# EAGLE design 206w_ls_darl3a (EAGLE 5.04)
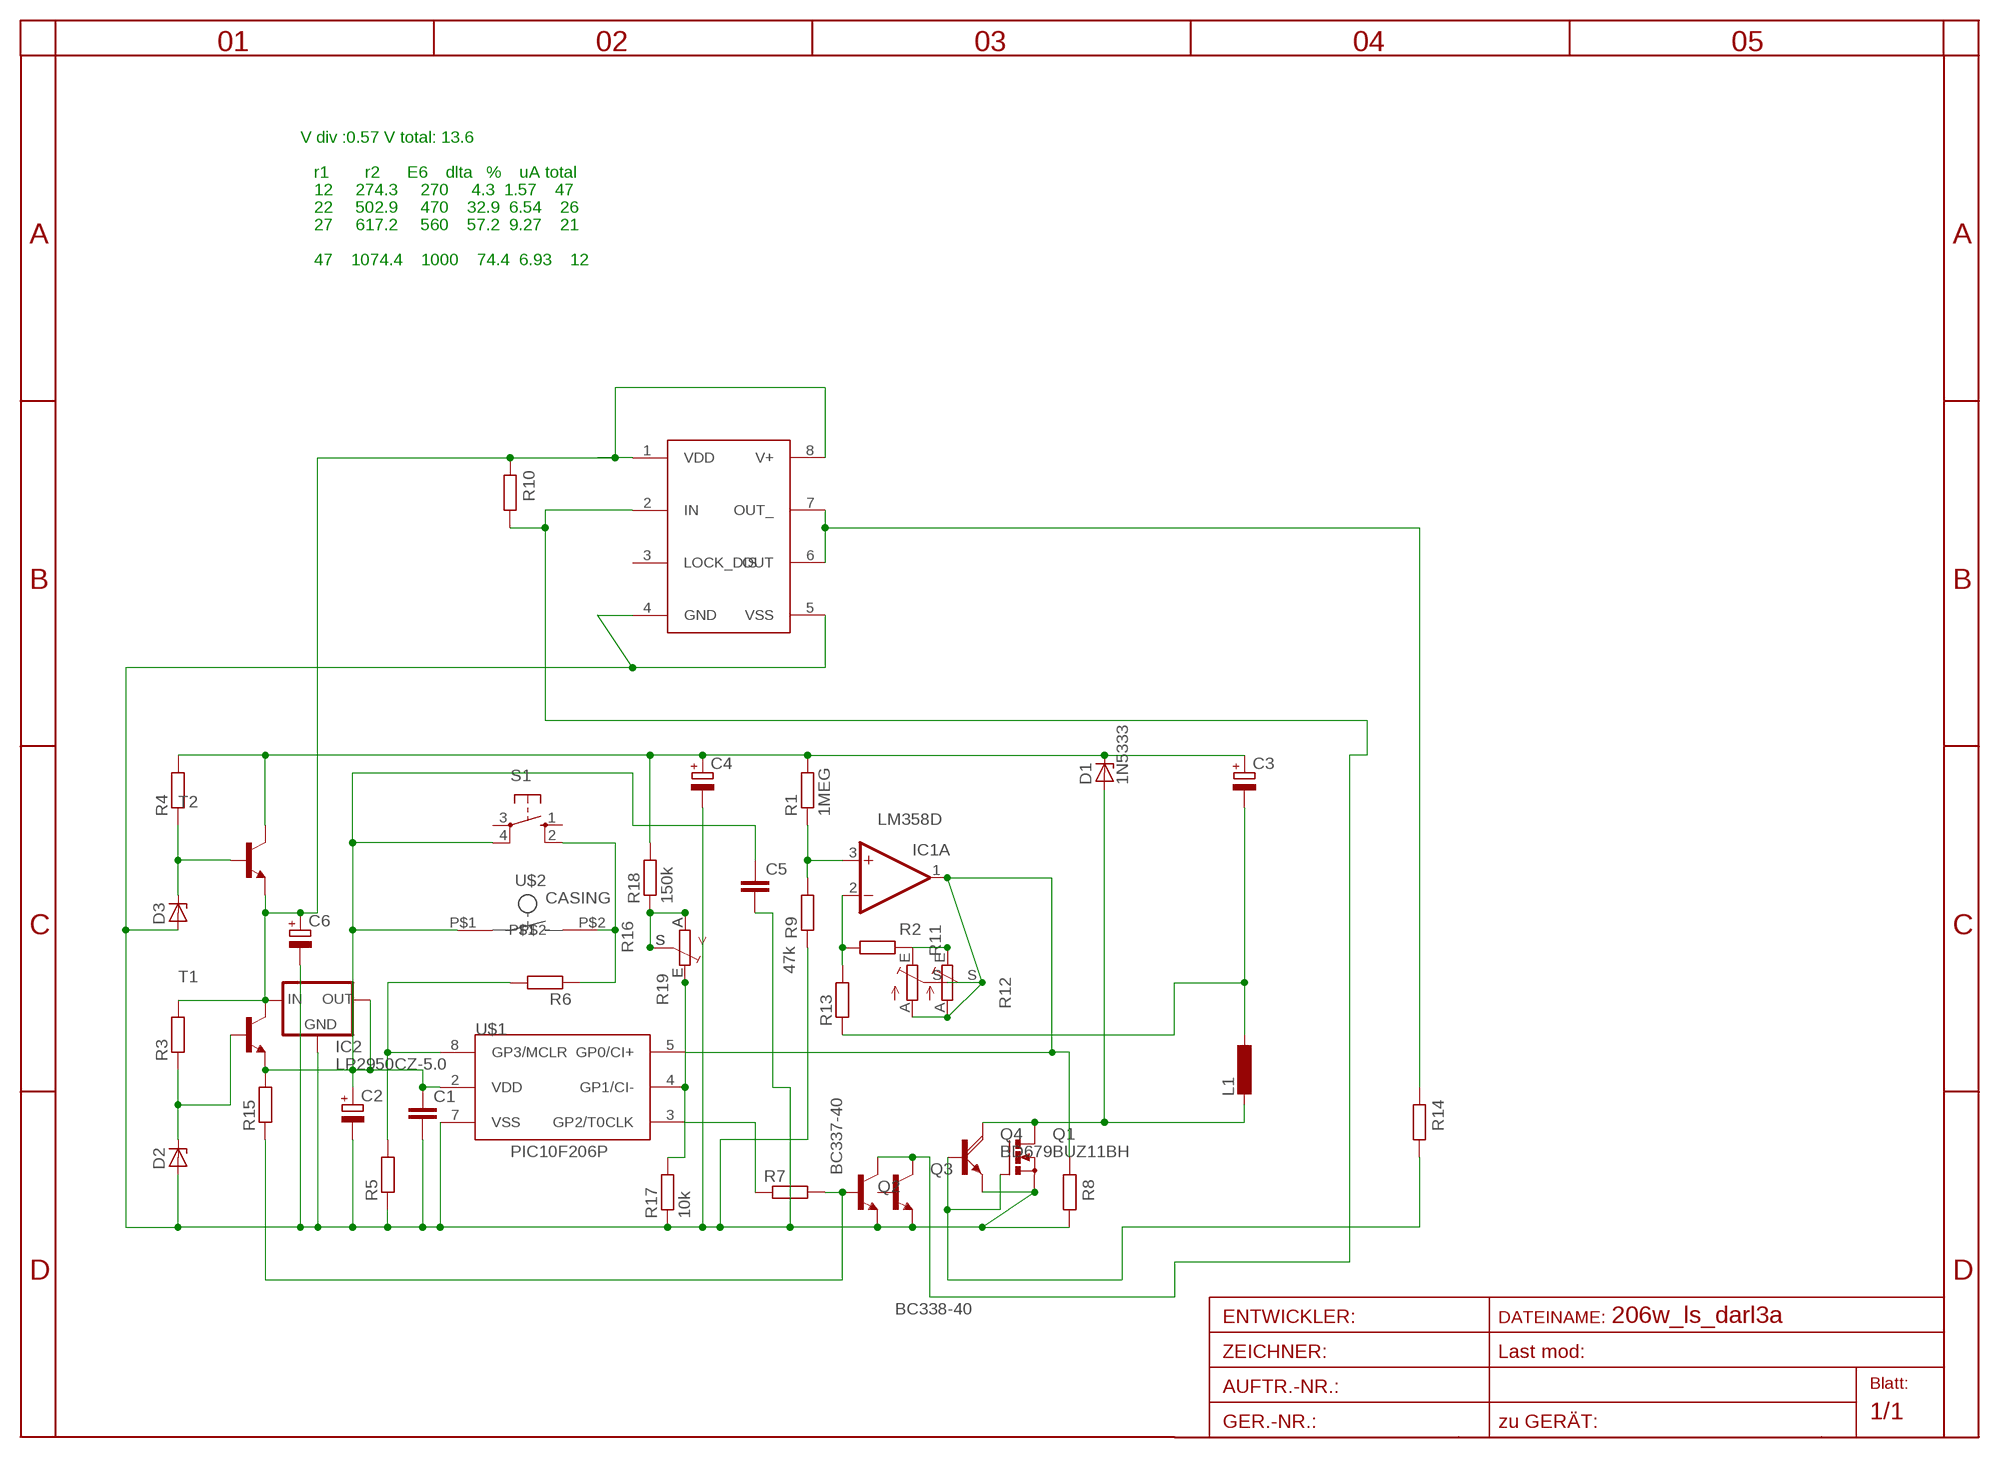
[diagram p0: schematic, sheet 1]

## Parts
C1  C-EU025-025X050  [C025-025X050]
C2  CPOL-EUE3.5-8  [E3,5-8]
C3  CPOL-EUE5-8.5  [E5-8,5]
C4  CPOL-EUE5-8.5  [E5-8,5]
C5  C-EU050-024X044  [C050-024X044]
C6  CPOL-EUE3.5-8  [E3,5-8]
D1  1N5333  [C1702-15]
D2  ZENER-DIODEZD-7.5  [ZDIO-7.5]
D3  ZENER-DIODEZD-7.5  [ZDIO-7.5]
IC1  LM358D  [SO08]
IC2  LP2950CZ-5.0  [TO92]
IC3  TC4432X  [SO-08]
L1  L-EU0207/10  [0207/10]
Q1  BUZ11BH  [TO220BH]
Q2  BC337-40  [TO92]
Q3  BC338-40  [TO92-EBC]
Q4  BD679  [TO126AV]
R1  1MEG  R-EU_0207/12  [0207/12]
R2  R-EU_0204/7  [0204/7]
R3  R-EU_0204/7  [0204/7]
R4  R-EU_0207/10  [0207/10]
R5  R-EU_0204/7  [0204/7]
R6  R-EU_0204/7  [0204/7]
R7  R-EU_0207/15  [0207/15]
R8  R-EU_0204/7  [0204/7]
R9  47k  R-EU_0204/7  [0204/7]
R10  R-EU_0204/7  [0204/7]
R11  TRIM_EU-CA6V  [CA6V]
R12  TRIM_EU-LI15  [LI15]
R13  R-EU_0207/40  [0207/40]
R14  R-EU_0204/2V  [0204V]
R15  R-EU_0204/5  [0204/5]
R16  TRIM_EU-LI15  [LI15]
R17  10k  R-EU_0204/7  [0204/7]
R18  150k  R-EU_0207/40  [0207/40]
R19  TRIM_EU-CA6V  [CA6V]
S1  10-XX  [B3F-10XX]
T1  -NPN-TO92-BCE  [TO92-BCE]
T2  -NPN-TO92-BCE  [TO92-BCE]
U$1  PIC10F206P  [DIL8]
U$2  CASING  [CASING]

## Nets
BB: IC3.2(IN) Q2.3(C) Q3.C R10.1
HOTSPOT: D1.A L1.2 Q1.D Q4.C
N$1: IC1.1(A:OUT) R8.2 R11.A R11.S R12.A R12.S U$1.5(GP0/CI+)
N$2: R2.1 R11.E R12.E
N$3: Q1.G Q4.B R14.1
N$5: R5.2 R6.2 U$1.8(GP3/MCLR)
N$6: D2.C R3.1 T1.B
N$7: R6.1 S1.2(S1) U$2.P$2
N$8: IC1.3(A:+IN) R1.1 R9.2
N$9: R7.1 U$1.3(GP2/T0CLK)
N$11: IC3.6(OUT) IC3.7(OUT_) R14.2
N$12: D3.C R4.1 T2.B
N$13: R16.A R16.S R18.1 R19.A R19.S
N$14: R16.E R17.2 R19.E U$1.4(GP1/CI-)
N$15: IC1.2(A:-IN) R2.2 R13.2
N$17: Q2.2(B) R7.2 R15.1
V60: C3.+ C4.+ D1.C R1.2 R4.2 R18.2 T2.C
V+: C1.1 C2.+ C5.1 IC2.1(OUT) R15.2 S1.4(P1) T1.E U$1.2(VDD) U$2.P$1
V-: C1.2 C2.- C4.- C5.2 C6.- D2.A D3.A IC2.2(GND) IC3.4(GND) IC3.5(VSS) Q1.S Q2.1(E) Q3.E Q4.E R5.1 R8.1 R9.1 R17.1 U$1.7(VSS)
VCC: C6.+ IC2.3(IN) IC3.1(VDD) IC3.8(V+) R3.2 R10.2 T1.C T2.E
VOUT: C3.- L1.1 R13.1
Unconnected: IC1.5(B:+IN) IC1.6(B:-IN) IC1.7(B:OUT) IC3.3(LOCK_DIS) Q3.B S1.1(S) S1.3(P)

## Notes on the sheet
- V div :0.57 V total: 13.6
- r1        r2      E6    dlta   %    uA total
- 12     274.3     270     4.3  1.57    47
- 22     502.9     470    32.9  6.54    26
- 27     617.2     560    57.2  9.27    21
- 47    1074.4    1000    74.4  6.93    12

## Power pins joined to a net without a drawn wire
V+: IC1.8(P:V+)
V-: IC1.4(P:V-)

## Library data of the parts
C1 C5 = rcl:C-EU: CAPACITOR, European symbol
C2-C4 C6 = rcl:CPOL-EU: POLARIZED CAPACITOR, European symbol
D1 = diode-1:1N5333: Z DIODE
D2 D3 = diode-1:ZENER-DIODE: Z-Diode
IC1 = linear4:LM358: OP AMP
IC2 = v-reg:LP2950?*: Source: http://cache.national.com/ds/LP/LP2950.pdf
IC3 = microchip:TC4432
L1 = rcl:L-EU: INDUCTOR, European symbol
Q1 = transistor-power:BUZ11: N-CHANNEL MOS FET
Q2 = transistor-npn:BC337*: NPN Transistor
Q3 = transistor-npn:BC338*: NPN Transistor
Q4 = transistor-power:BD679: NPN DARLINGTON TRANSISTOR
R1-R6 R8-R10 R14 R15 = rcl:R-EU_: RESISTOR, European symbol
R7 R13 R17 R18 = rcl-2:R-EU_: RESISTOR, European symbol
R11 R12 R16 R19 = pot:TRIM_EU-: POTENTIOMETER
S1 = switch-omron:10-XX: OMRON SWITCH
T1 T2 = transistor-neu-to92:*-NPN-: NPN Transistror
U$1 = microchip-5:PIC10F2*: uPC nW 0,25/0,5k Program Flash memory Comparator
U$2 = button:CASING

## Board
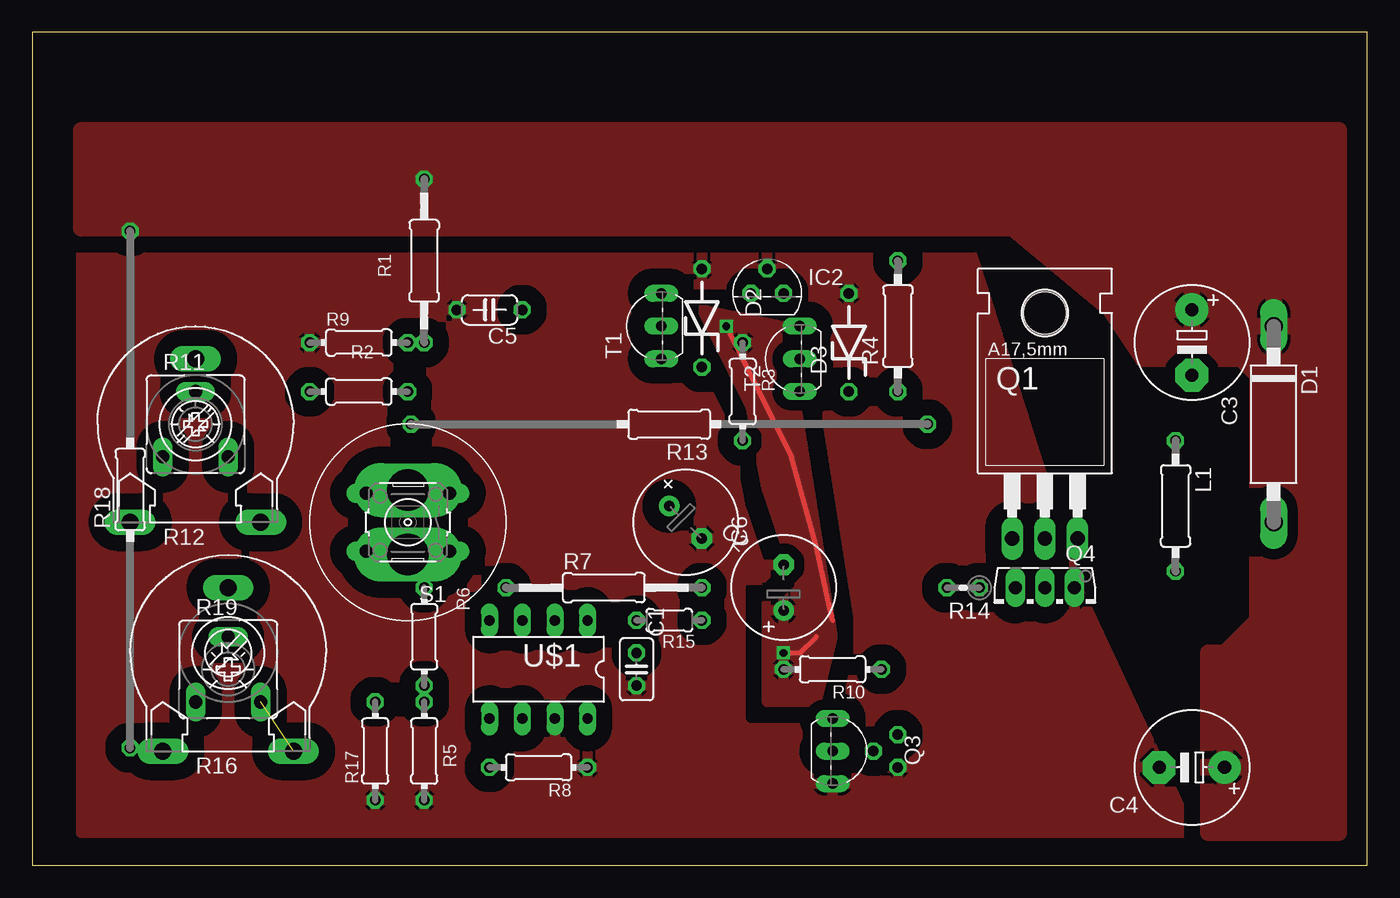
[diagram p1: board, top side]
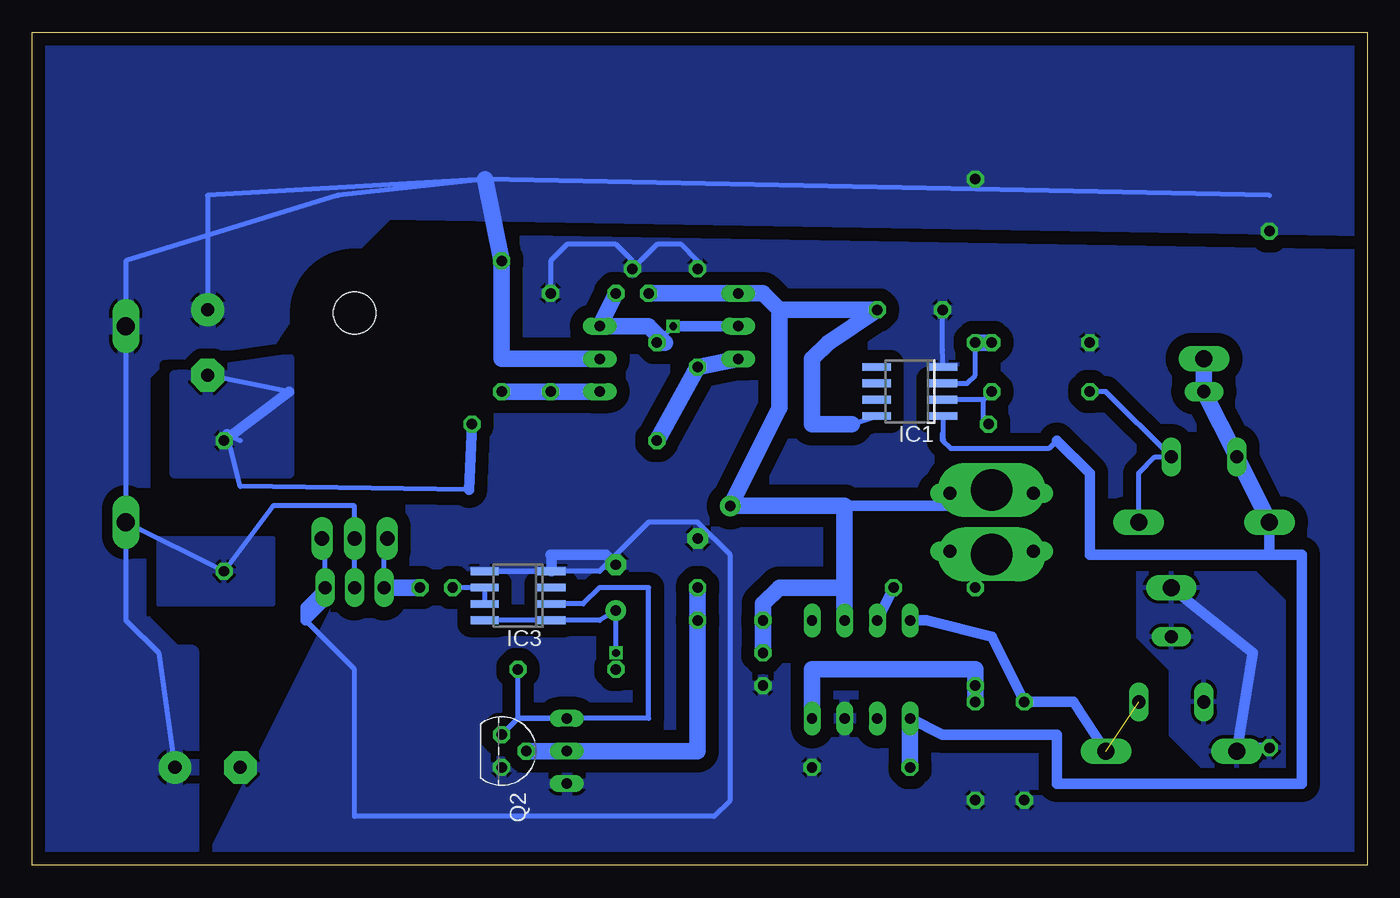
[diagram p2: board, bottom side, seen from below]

Size 103.81 x 64.76 mm. Coordinates in mm from the lower left corner, seen from the top.
Outline: 0,0 103.81,0 103.81,64.76 0,64.76 0,0
Copper layers (1*16): Top 0.035mm / dielectric 1.5mm / Bottom 0.035mm
Design rules "default": minimum track width 10mil, minimum drill 24mil, track to track 8mil, track to pad 8mil, pad to pad 8mil, via to via 8mil, smd to smd 8mil, copper to edge 40mil, drill to drill 8mil, minimum pad ring 10mil, minimum via ring 8mil, stop-mask expansion 4mil, vias tented up to drill 0mil, thermal gap 10mil

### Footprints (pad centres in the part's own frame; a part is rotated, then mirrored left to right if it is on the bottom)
C025-025X050 = drill 0.813 octagon: 1 -1.27,0; 2 1.27,0
E3,5-8 = drill 0.813 pad 1.6 round: + -1.778,0 | drill 0.813 pad 1.6 octagon: - 1.778,0
E5-8,5 = drill 1.016 pad 2.54 round: + -2.54,0 | drill 1.016 pad 2.54 octagon: - 2.54,0
C050-024X044 = drill 0.813 octagon: 1 -2.54,0; 2 2.54,0
C1702-15 = drill 1.397 long: A 7.62,0; C -7.62,0
ZDIO-7.5 = drill 0.813 octagon: A 3.81,0; C -3.81,0
SO08 = smd 0.6 x 2.2: 1 -1.905,-2.6; 2 -0.635,-2.6; 3 0.635,-2.6; 4 1.905,-2.6; 5 1.905,2.6; 6 0.635,2.6; 7 -0.635,2.6; 8 -1.905,2.6
TO92 = drill 0.813 octagon: 1 -1.27,0; 2 0,1.905; 3 1.27,0
SO-08 = smd 0.6 x 2.2: 1 -1.905,-2.6; 2 -0.635,-2.6; 3 0.635,-2.6; 4 1.905,-2.6; 5 1.905,2.6; 6 0.635,2.6; 7 -0.635,2.6; 8 -1.905,2.6
0207/10 = drill 0.813 octagon: 1 -5.08,0; 2 5.08,0
TO220BH = drill 1.118 long: D 0,-6.35; G -2.54,-6.35; S 2.54,-6.35 | hole 3.302: 0,11.176
TO92' = drill 0.813 octagon: 1 1.27,0; 2 0,1.905; 3 -1.27,0
TO92-EBC = drill 0.813 long: B 0,-1.27; C -2.54,-1.27; E 2.54,-1.27
TO126AV = drill 1.016 long: B 2.286,-1.27; C 0,-1.27; E -2.286,-1.27
0207/12 = drill 0.813 octagon: 1 -6.35,0; 2 6.35,0
0204/7 = drill 0.813 octagon: 1 -3.81,0; 2 3.81,0
0207/15 = drill 0.813 octagon: 1 -7.62,0; 2 7.62,0
CA6V = drill 1.016 long: A -2.54,-2.54; E 2.54,-2.54; S 0,2.54
LI15 = drill 1.321 long: A -5.08,-7.62; E 5.08,-7.62; S 0,5.08
0207/40 = drill 0.813 octagon: 1 -20.08,0; 2 20.08,0
0204V = drill 0.813 octagon: 1 -1.27,0; 2 1.27,0
0204/5 = drill 0.813 octagon: 1 -2.54,0; 2 2.54,0
B3F-10XX = drill 1.016 long: 1 -3.251,2.261; 2 3.251,2.261; 3 -3.251,-2.261; 4 3.251,-2.261
TO92-BCE = drill 0.813 long: B -2.54,0; C 0,0; E 2.54,0
DIL8 = drill 0.813 long: 1 -3.81,-3.81; 2 -1.27,-3.81; 3 1.27,-3.81; 4 3.81,-3.81; 5 3.81,3.81; 6 1.27,3.81; 7 -1.27,3.81; 8 -3.81,3.81
CASING = drill 3.2 pad 3.81 long: P$1 -2.5,0; P$2 2.5,0

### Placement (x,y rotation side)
C1  46.99,15.24 270 top
C2  50.8,26.67 315 top
C3  90.17,40.64 270 top
C4  90.17,7.62 180 top
C5  35.56,43.18 180 top
C6  58.42,21.59 90 top
D1  96.52,34.29 270 top
D2  52.07,42.55 90 top
D3  63.5,40.64 90 top
IC1  35.56,36.83 90 bottom
IC2  57.15,44.45 0 top
IC3  66.04,20.95 90 bottom
L1  88.9,27.94 270 top
Q1  78.74,31.75 0 top
Q2  BC337-40  [TO92']  67.31,8.89 270 bottom
Q3  63.5,8.89 270 top
Q4  78.74,20.32 180 top
R1  30.48,46.99 90 top
R2  25.4,36.83 0 top
R3  55.24,36.83 90 top
R4  67.31,41.91 90 top
R5  30.48,8.89 90 top
R6  30.48,17.78 270 top
R7  44.45,21.59 0 top
R8  39.37,7.62 180 top
R9  25.4,40.64 0 top
R10  62.23,15.24 180 top
R11  12.7,34.29 0 top
R12  12.7,34.29 0 top
R13  49.53,34.29 180 top
R14  72.39,21.59 180 top
R15  49.53,19.05 180 top
R16  15.24,16.51 0 top
R17  26.67,8.89 90 top
R18  7.62,29.21 90 top
R19  15.24,15.24 0 top
S1  29.21,26.67 180 top
T1  48.9,41.91 90 top
T2  59.69,39.37 90 top
U$1  39.37,15.24 180 top
U$2  29.21,26.67 270 top

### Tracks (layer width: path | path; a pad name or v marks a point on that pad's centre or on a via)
BB
  Bottom 0.406: 66.04,11.43 Q2.3 | 66.04,11.43 Q3.C | 66.04,11.43 55.88,11.43 55.88,21.59 59.69,21.59 60.96,20.32 IC3.2 | 66.04,11.43 R10.1
HOTSPOT
  Bottom 0.406: D1.A L1.2 85.09,27.94 78.74,27.94 Q1.D Q4.C 78.74,20.32
  pour Bottom (isolate 0.813, rank 3): 85.09,25.4 93.98,25.4 93.98,20.32 85.09,20.32
N$1
  Bottom 0.406: 33.02,33.02 33.02,33.61 | IC1.1 32.96,33.08 33.02,33.02 | 33.02,33.02 32.38,32.38 24.77,32.38 24.13,33.02
  Bottom 0.813: 24.13,33.02 21.59,30.48 21.59,24.13 7.62,24.13 | 7.62,24.13 R12.A | U$1.5 33.02,10.16 24.13,10.16 24.13,6.35 5.08,6.35 5.08,24.13 7.62,24.13
  Bottom 1.27: R12.A R11.A R11.S R12.S | U$1.5 R8.2
N$2
  Bottom 0.406: R2.1 20.32,36.83 R11.E 16.51,31.75 17.78,30.48 R12.E
N$3
  Bottom 0.406: Q4.B 76.45,25.15 Q1.G
  Bottom 1.27: R14.1 Q4.B
N$5
  Bottom 1.27: U$1.8 43.18,15.24 30.48,15.24 R6.2 R5.2
N$6
  Bottom 1.27: R3.1 D2.C T1.B
N$7
  Bottom 0.813: S1.2 26.2,24.17 U$2.P$2 30.48,22.9 R6.1
N$8
  Bottom 0.406: R1.1 30.48,38.1 31.11,37.47 IC1.3
  Bottom 1.27: R1.1 R9.2
N$9
  Bottom 0.813: R7.1 U$1.3
N$11
  Bottom 0.406: R14.2 IC3.6 IC3.7
N$12
  Bottom 0.406: D3.C R4.1
  Bottom 1.27: T2.B D3.C R4.1
N$13
  Bottom 0.813: R18.1 8.89,9.13 R16.A 8.89,16.51 R16.S
  pour Bottom (isolate 0.813, rank 2): 17.78,20.32 17.78,22.86 8.89,22.86 6.35,20.32 6.35,6.35 11.43,6.35 15.24,10.16 15.24,15.24 17.78,17.78
N$14  (1 unrouted)
  Bottom 0.813: R16.E 22.86,12.7 R17.2 29.21,17.78 34.29,19.05 U$1.4
N$15
  Bottom 0.406: 29.37,36.99 R2.2 29.84,36.2 | 29.84,36.2 IC1.2 | 29.84,36.2 29.84,34.69 R13.2
N$17
  Bottom 0.406: R15.1 R7.2
  Bottom 1.27: Q2.2 52.07,8.89 R15.1 R7.2
V60
  Bottom 0.406: C4.+ 93.98,16.51 96.52,19.05 96.52,46.99 80.01,52.07 68.58,53.34 | 7.62,52.07 68.58,53.34 | 68.58,53.34 90.17,52.07 C3.+
  Bottom 1.27: 68.58,53.34 R4.2 67.31,39.37 T2.C
  pour Bottom (isolate 0.813, rank 4): 0,64.77 102.87,63.5 102.87,1.27 91.44,1.27 91.44,16.51 92.71,16.51 95.25,19.05 95.25,38.1 93.98,39.37 86.36,39.37 83.82,43.18 76.2,50.8 0,49.53
  pour Top (isolate 0.813, rank 4): 3.81,57.15 101.6,57.15 101.6,2.54 91.44,2.54 91.44,16.51 92.71,16.51 95.25,19.05 95.25,38.1 93.98,39.37 86.36,39.37 83.82,43.18 76.2,49.53 3.81,49.53
V+
  Bottom 0.406: 40.06,34.29 IC1.8 | 46.99,44.45 T1.E | C2.+ | C2.+
  Bottom 0.813: 40.64,27.94 31.75,27.94 31.75,29.21 | S1.4 31.47,28.93 31.75,29.21 | 31.75,29.21 31.71,29.17 U$2.P$1
  Bottom 1.27: 40.64,21.59 U$1.2 | 45.72,43.18 45.72,35.56 C2.+ 40.64,27.94 40.64,21.59 | 45.72,43.18 C5.1 41.91,40.64 43.18,39.37 43.18,34.29 40.06,34.29 | C1.1 R15.2 46.99,20.32 45.72,21.59 40.64,21.59 | 45.72,43.18 46.99,44.45 IC2.1
V-
  Bottom 0.406: C5.2 33.02,40.06 IC1.4 | IC3.4 IC3.5 59.69,22.86 55.88,26.67 52.07,26.67 49.53,24.13 49.53,5.08 50.8,3.81 78.74,3.81 78.74,15.24 82.55,19.05 | D2.A 52.07,46.99 53.34,48.26 55.24,48.26 IC2.2 57.15,46.99 58.42,48.26 62.23,48.26 63.5,46.99 D3.A | Q4.E 81.03,25.15 Q1.S
  Bottom 0.813: Q4.E 82.55,20.07 82.55,19.05 81.03,20.57 | C6.- 59.18,24.13 63.5,24.13 63.44,24.07 IC3.4
  pour Bottom (isolate 1.016, rank 5): 68.58,49.53 80.01,20.32 90.17,0 1.27,1.27 1.27,48.26
  pour Top (isolate 1.27, rank 5): 72.39,49.53 81.28,21.59 90.17,2.54 3.81,2.54 3.81,49.53
VCC  (via drill 0.6)
  Top 0.406: v58.42,16.51 59.69,16.51 60.96,17.78 | v53.98,41.91 59.05,31.75 60.96,24.77 62.23,19.05
  Bottom 0.406: v58.42,16.51 C6.+ 59.69,19.05 IC3.1 IC3.8 | v53.98,41.91 R3.2
  Bottom 0.813: v53.98,41.91 T1.C
  Bottom 1.27: IC2.3 T2.E 55.88,41.91 54.61,40.64 R3.2
  pour Top (isolate 0.813): 52.07,43.18 58.42,41.91 62.23,17.78 60.96,12.7 57.15,12.7 57.15,20.32 58.42,20.32 59.69,21.59 57.15,29.21 55.88,35.56
VOUT
  Bottom 0.406: 87.63,33.02 88.65,33.53 87.63,29.46 69.85,29.21 | 83.82,36.83 C3.-
  Bottom 0.813: 88.65,33.53 L1.1 83.82,36.83 | 69.85,29.21 R13.1
  pour Bottom (isolate 0.813): 83.82,39.37 92.71,38.1 92.71,30.48 83.82,30.48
